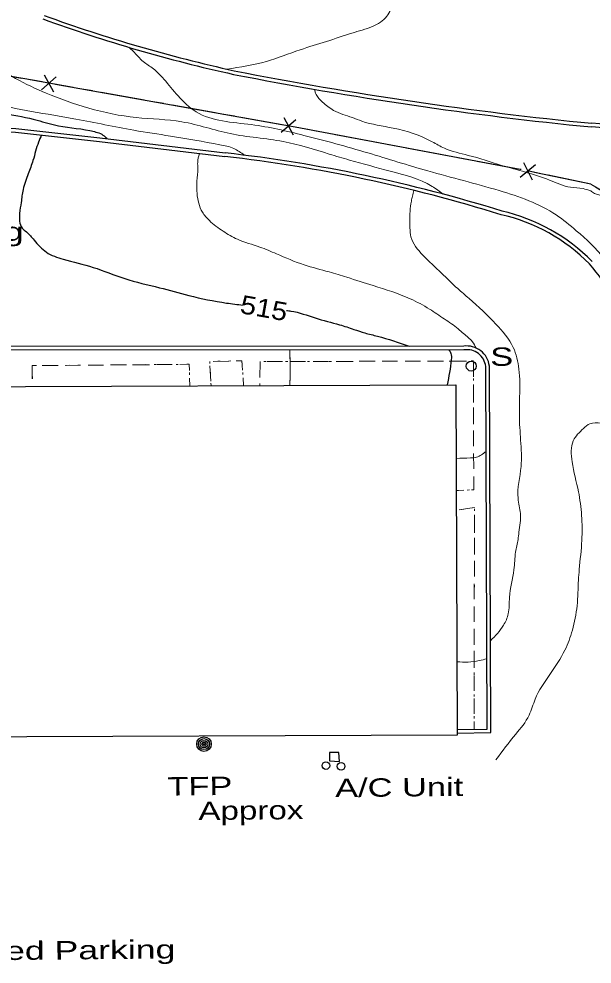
# Model space of a CAD drawing. Extents: x 2362213 to 2366494, y 6968794 to 6978110.
# Drawn here: x 2363724.2 to 2363873.9, y 6976167.5 to 6976414.2 of the extents above; entities that cross this region are included whole.
import ezdxf
from ezdxf.enums import TextEntityAlignment as Align

# ---------------------------------------------------------------- set-up
doc = ezdxf.new("R2010")
doc.units = 0
doc.header["$LTSCALE"] = 1.9
for name, pattern in [('DOTTED', [1.5, 0.3, -1.2]), ('LONG_DASH_SHORT_DASH', [9.9, 6, -1.2, 1.5, -1.2]), ('SHORT_DASHED', [2.7, 1.5, -1.2])]:
    doc.linetypes.add(name, pattern=pattern)
for name, color, linetype, lineweight in [('11', 7, 'Continuous', 25), ('13', 7, 'Continuous', 13), ('17', 7, 'Continuous', 25), ('2', 7, 'Continuous', 25), ('20', 7, 'Continuous', 25), ('21', 7, 'Continuous', 25), ('23', 7, 'Continuous', 25), ('31', 7, 'Continuous', 25), ('35', 7, 'Continuous', 13), ('36', 7, 'Continuous', 13)]:
    doc.layers.add(name, color=color, linetype=linetype, lineweight=lineweight)

msp = doc.modelspace()

# ---------------------------------------------------------------- linework, layer by layer
at = {"layer": '11'}
msp.add_lwpolyline([(2363568.529, 6976317.655), (2363838.301, 6976318.715), (2363838.662, 6976227.293), (2363568.89, 6976226.234)], close=True, dxfattribs=at)
at = {"layer": '13'}
for p, q in [((2363778.9, 6976324.898), (2363774.901, 6976324.81)), ((2363823.042, 6976324.839), (2363819.042, 6976324.831)), ((2363829.043, 6976324.866), (2363825.042, 6976324.848)), ((2363835.043, 6976324.883), (2363831.042, 6976324.875)), ((2363841.043, 6976324.9), (2363837.043, 6976324.892)), ((2363734.249, 6976323.743), (2363730.249, 6976323.715)), ((2363740.248, 6976323.79), (2363736.249, 6976323.762)), ((2363746.249, 6976323.838), (2363742.248, 6976323.809)), ((2363752.248, 6976323.895), (2363748.248, 6976323.857)), ((2363758.248, 6976323.942), (2363754.248, 6976323.914)), ((2363764.247, 6976323.999), (2363760.247, 6976323.961)), ((2363774.081, 6976323.673), (2363774.299, 6976319.674)), ((2363787.182, 6976324.587), (2363787.12, 6976320.587)), ((2363793.042, 6976324.743), (2363789.041, 6976324.735)), ((2363799.042, 6976324.76), (2363795.042, 6976324.752)), ((2363805.042, 6976324.787), (2363801.042, 6976324.769)), ((2363811.041, 6976324.805), (2363807.041, 6976324.796)), ((2363817.042, 6976324.822), (2363813.042, 6976324.814)), ((2363842.873, 6976320.727), (2363842.864, 6976324.728)), ((2363768.841, 6976318.443), (2363768.772, 6976320.442)), ((2363782.851, 6976318.497), (2363782.722, 6976320.495)), ((2363787.089, 6976318.587), (2363787.09, 6976318.517)), ((2363842.89, 6976314.728), (2363842.882, 6976318.728)), ((2363842.917, 6976308.728), (2363842.899, 6976312.728)), ((2363842.934, 6976302.727), (2363842.926, 6976306.728)), ((2363842.951, 6976296.727), (2363842.943, 6976300.727)), ((2363838.415, 6976291.095), (2363840.414, 6976291.184)), ((2363843.077, 6976286.669), (2363839.133, 6976286.021)), ((2363843.163, 6976280.788), (2363843.175, 6976284.79)), ((2363843.14, 6976274.788), (2363843.152, 6976278.788)), ((2363843.127, 6976268.789), (2363843.139, 6976272.789)), ((2363843.104, 6976262.788), (2363843.116, 6976266.788)), ((2363843.091, 6976256.787), (2363843.103, 6976260.788)), ((2363843.079, 6976250.786), (2363843.09, 6976254.787)), ((2363843.066, 6976244.787), (2363843.078, 6976248.787)), ((2363843.053, 6976238.786), (2363843.065, 6976242.787)), ((2363843.04, 6976232.785), (2363843.052, 6976236.785)), ((2363843.038, 6976228.785), (2363843.039, 6976230.785))]:
    msp.add_line(p, q, dxfattribs=at)
at = {"layer": '13', "linetype": 'DOTTED'}
for points in [[(2363782.851, 6976318.497), (2363782.419, 6976324.972), (2363774.021, 6976324.792), (2363774.371, 6976318.466)], [(2363838.415, 6976291.095), (2363842.973, 6976291.288), (2363842.863, 6976324.908), (2363787.181, 6976324.727), (2363787.09, 6976318.517)], [(2363768.841, 6976318.443), (2363768.648, 6976324.041), (2363727.679, 6976323.691), (2363727.691, 6976318.281)], [(2363843.038, 6976228.785), (2363843.177, 6976286.69), (2363838.434, 6976285.905)]]:
    msp.add_lwpolyline(points, dxfattribs=at)
at = {"layer": '13'}
for points in [[(2363782.583, 6976322.493), (2363782.419, 6976324.972), (2363780.9, 6976324.938)], [(2363728.249, 6976323.696), (2363727.679, 6976323.691), (2363727.682, 6976320.261)], [(2363768.703, 6976322.441), (2363768.648, 6976324.041), (2363766.247, 6976324.018)], [(2363842.413, 6976291.263), (2363842.973, 6976291.288), (2363842.96, 6976294.728)]]:
    msp.add_lwpolyline(points, dxfattribs=at)
at = {"layer": '17'}
for p, q in [((2363733.902, 6976399.064), (2363730.054, 6976395.688)), ((2363730.756, 6976399.624), (2363733.199, 6976395.127)), ((2363792.833, 6976386.555), (2363733.761, 6976397.083)), ((2363796.531, 6976387.88), (2363792.653, 6976384.533)), ((2363793.385, 6976388.47), (2363795.798, 6976383.943)), ((2363855.94, 6976376.735), (2363858.253, 6976372.167)), ((2363859.066, 6976376.085), (2363855.116, 6976372.827)), ((2363873.545, 6976371.043), (2363858.865, 6976374.113))]:
    msp.add_line(p, q, dxfattribs=at)
at = {"layer": '17', "linetype": 'LONG_DASH_SHORT_DASH'}
for points in [[(2363873.545, 6976371.043), (2363855.076, 6976374.907), (2363793.915, 6976386.365), (2363719.615, 6976399.608), (2363641.073, 6976414.261), (2363572.252, 6976426.636), (2363526.035, 6976435.556), (2363495.913, 6976440.79), (2363481.574, 6976443.734), (2363473.602, 6976444.928), (2363465.401, 6976443.98)], [(2363873.545, 6976371.043), (2363874.811, 6976370.385), (2363881.511, 6976366.277), (2363884.852, 6976362.97), (2363889.388, 6976357.143), (2363895.017, 6976347.796), (2363898.908, 6976336.183), (2363906.246, 6976314.412), (2363913.758, 6976296.292), (2363920.544, 6976281.085), (2363939.363, 6976255.993), (2363960.385, 6976230.752), (2363984.072, 6976199.658)]]:
    msp.add_lwpolyline(points, dxfattribs=at)
at = {"layer": '17'}
for points in [[(2363730.214, 6976397.719), (2363719.615, 6976399.608), (2363671.217, 6976408.638)], [(2363855.337, 6976374.85), (2363855.076, 6976374.907), (2363796.37, 6976385.909)], [(2363873.545, 6976371.043), (2363874.811, 6976370.385), (2363881.511, 6976366.277), (2363884.852, 6976362.97), (2363885.47, 6976362.166)]]:
    msp.add_lwpolyline(points, dxfattribs=at)
at = {"layer": '2'}
for p, q in [((2363840.346, 6976328.765), (2363565.553, 6976328.658)), ((2363840.345, 6976327.805), (2363565.553, 6976327.698))]:
    msp.add_line(p, q, dxfattribs=at)
for points in [[(2363716.905, 6976384.842), (2363723.299, 6976384.623), (2363745.203, 6976382.161), (2363777.962, 6976378.253)], [(2363716.936, 6976385.802), (2363723.37, 6976385.583), (2363745.314, 6976383.112), (2363778.073, 6976379.204)], [(2363838.639, 6976228.703), (2363846.498, 6976228.858), (2363846.086, 6976323.578)], [(2363838.658, 6976227.743), (2363847.467, 6976227.917), (2363847.045, 6976323.587)]]:
    msp.add_lwpolyline(points, dxfattribs=at)
for centre, radius, start, end in [((2363865.346, 6976785.483), 395.058, 250.03282, 257.55374), ((2363865.346, 6976785.483), 394.098, 250.03282, 257.55374), ((2363971.891, 6977379.515), 998.38, 258.93176, 264.35807), ((2363971.891, 6977379.515), 997.42, 258.93176, 264.35807), ((2363446.466, 6970015.596), 6385.647, 85.88154, 86.16254), ((2363446.466, 6970015.596), 6384.687, 85.88154, 86.16254), ((2363733.974, 6975989.821), 391.874, 72.71881, 83.53909), ((2363733.974, 6975989.821), 390.914, 72.71881, 83.53909), ((2363839.683, 6976317.272), 46.986, 44.52251, 77.19154), ((2363839.683, 6976317.272), 47.946, 44.52251, 77.19154), ((2363837.348, 6976318.237), 48.031, 15.6658, 41.74776), ((2363841.145, 6976322.875), 5.944, 6.89231, 97.72428), ((2363841.145, 6976322.875), 4.984, 6.89231, 97.72428)]:
    msp.add_arc(centre, radius, start, end, dxfattribs=at)
at = {"layer": '20'}
for radius in [1.9, 1.442, 0.973, 0.539, 0.192]:
    msp.add_circle((2363772.511, 6976224.914), radius, dxfattribs=at)
at = {"layer": '21'}
msp.add_circle((2363842.315, 6976323.573), 1.3, dxfattribs=at)
at = {"layer": '23'}
msp.add_lwpolyline([(2363805.274, 6976222.746), (2363805.294, 6976220.596), (2363807.895, 6976220.421), (2363807.743, 6976222.759)], close=True, dxfattribs=at)
for centre in [(2363804.356, 6976219.327), (2363808.318, 6976219.124)]:
    msp.add_circle(centre, 1, dxfattribs=at)
at = {"layer": '31'}
for points in [[(2363687.536, 6976396.303), (2363692.366, 6976395.199), (2363700.808, 6976393.019), (2363710.362, 6976390.529), (2363720.773, 6976389.348), (2363728.939, 6976387.727), (2363734.514, 6976386.27), (2363743.907, 6976384.769), (2363746.732, 6976383.376), (2363747.126, 6976382.9)], [(2363730.096, 6976383.857), (2363729.294, 6976382.01), (2363727.859, 6976377.246), (2363726.592, 6976373.754), (2363725.281, 6976369.681), (2363724.754, 6976366.245), (2363724.371, 6976363.402), (2363725.047, 6976359.598), (2363726.137, 6976358.599), (2363728.137, 6976356.458), (2363731.367, 6976353.288), (2363735.715, 6976351.479), (2363743.565, 6976349.344), (2363751.814, 6976346.402), (2363760.866, 6976344.028), (2363768.587, 6976342.001), (2363778.386, 6976340.035), (2363782.711, 6976339.486)], [(2363794.085, 6976338.075), (2363795.217, 6976337.935), (2363801.544, 6976336.146), (2363807.94, 6976334.356), (2363811.663, 6976333.162), (2363814.532, 6976332.219), (2363817.82, 6976331.38), (2363826.085, 6976328.759)], [(2363836.505, 6976327.808), (2363837.024, 6976326.853), (2363837.089, 6976325.253), (2363836.052, 6976318.703)]]:
    msp.add_spline(points, degree=3, dxfattribs=at)
at = {"layer": '35'}
for points in [[(2363665.808, 6976435.897), (2363665.919, 6976434.768), (2363666.153, 6976433.191), (2363666.314, 6976430.992), (2363666.145, 6976426.72), (2363665.963, 6976424.849), (2363665.087, 6976420.2), (2363663.69, 6976415.717), (2363662.882, 6976412.358), (2363662.713, 6976411.206), (2363663.338, 6976409.593), (2363666.495, 6976407.783), (2363676.361, 6976403.967), (2363689.155, 6976400.638), (2363697.557, 6976398.178), (2363713.631, 6976393.721), (2363716.36, 6976392.717), (2363727.497, 6976390.022), (2363739.046, 6976388.042), (2363754.215, 6976385.117), (2363763.749, 6976383.598), (2363776.612, 6976381.35), (2363780.312, 6976380.355), (2363783.068, 6976378.612)], [(2363820.888, 6976430.354), (2363821.185, 6976428.567), (2363822.194, 6976425.516), (2363822.362, 6976423.598), (2363822.242, 6976421.547), (2363821.782, 6976418.322), (2363820.275, 6976414.878), (2363816.52, 6976412.211), (2363811.116, 6976410.46), (2363804.527, 6976408.287), (2363797.617, 6976406.121), (2363788.815, 6976403.087), (2363778.505, 6976401.069)], [(2363708.819, 6976422.297), (2363710.519, 6976421.253), (2363712.34, 6976420.1), (2363714.323, 6976418.729), (2363715.71, 6976416.852), (2363717.526, 6976414.199), (2363718.19, 6976408.545), (2363718.641, 6976405.299), (2363720.14, 6976401.123), (2363723.315, 6976398.644), (2363731.272, 6976394.839), (2363742.419, 6976390.884), (2363754.814, 6976388.442), (2363766.764, 6976387.327), (2363779.325, 6976384.246), (2363793.225, 6976382.178), (2363805.227, 6976378.903), (2363810.511, 6976377.353), (2363821.13, 6976374.454), (2363832.107, 6976370.468), (2363834.968, 6976368.454)], [(2363752.879, 6976406.775), (2363754.009, 6976405.756), (2363756.655, 6976403.051), (2363759.293, 6976401.176), (2363762.048, 6976398.432), (2363765.739, 6976394.097), (2363770.48, 6976389.911), (2363784.872, 6976386.579), (2363798.63, 6976383.79), (2363815.294, 6976379.218), (2363831.019, 6976374.498), (2363849.65, 6976369.364), (2363864.501, 6976363.026), (2363869.76, 6976358.896), (2363876.999, 6976351.595), (2363881.126, 6976344.713), (2363883.59, 6976340.127), (2363885.881, 6976332.669), (2363887.899, 6976323.466), (2363889.062, 6976316.828), (2363891.214, 6976306.088), (2363893.999, 6976296.104), (2363894.644, 6976288.3)], [(2363801.376, 6976395.807), (2363801.799, 6976394.431), (2363803.498, 6976392.477), (2363806.368, 6976390.283), (2363811.265, 6976388.431), (2363813.715, 6976387.504), (2363821.953, 6976385.672), (2363832.136, 6976382.129), (2363835.294, 6976380.419), (2363841.552, 6976378.568), (2363850.227, 6976375.961), (2363862.734, 6976372.12), (2363868.222, 6976370.252), (2363871.516, 6976369.893), (2363873.521, 6976369.352)], [(2363771.324, 6976379.04), (2363770.866, 6976376.715), (2363770.9, 6976375.216), (2363770.673, 6976371.813), (2363770.704, 6976368.542), (2363772.09, 6976363.746), (2363773.921, 6976361.544), (2363777.507, 6976358.778), (2363781.247, 6976356.673), (2363787.116, 6976354.619), (2363791.424, 6976352.88), (2363798.662, 6976349.999), (2363805.2, 6976348.141), (2363809.832, 6976346.744), (2363816.704, 6976344.589), (2363826.367, 6976341.132), (2363831.422, 6976338.44), (2363835.258, 6976335.877), (2363838.923, 6976333.281), (2363840.314, 6976332.065), (2363842.595, 6976329.956), (2363843.611, 6976328.286)], [(2363827.338, 6976369.422), (2363826.963, 6976367.908), (2363826.685, 6976366.635), (2363826.351, 6976363.893), (2363826.261, 6976361.772), (2363826.311, 6976359.643), (2363826.574, 6976357.275), (2363829.658, 6976352.534), (2363834.564, 6976347.831), (2363838.783, 6976343.8), (2363841.747, 6976341.219), (2363848.761, 6976334.545), (2363853.278, 6976328.458), (2363854.783, 6976322.781), (2363854.961, 6976315.613), (2363854.887, 6976310.812), (2363855.219, 6976304.225), (2363855.335, 6976297.325), (2363854.544, 6976289.068), (2363855.152, 6976285.084), (2363854.788, 6976280.189), (2363854.536, 6976278.317), (2363853.897, 6976275.02), (2363853.482, 6976270.437), (2363852.301, 6976263.196), (2363851.991, 6976258.921), (2363850.74, 6976255.959), (2363847.358, 6976251.867)], [(2363873.521, 6976369.352), (2363874.538, 6976368.651), (2363875.069, 6976368.476), (2363880.984, 6976364.843), (2363883.07, 6976363.213), (2363885.165, 6976356.403), (2363888.555, 6976346.894), (2363891.363, 6976340.831), (2363894.384, 6976329.269), (2363898.171, 6976318.035), (2363903.178, 6976307.872), (2363909.902, 6976295.906), (2363915.335, 6976281.917), (2363919.346, 6976271.354), (2363923.916, 6976260.937), (2363928.305, 6976253.678), (2363935.565, 6976244.228), (2363940.051, 6976236.279), (2363940.504, 6976232.773)], [(2363889.133, 6976305.158), (2363887.554, 6976306.033), (2363886.155, 6976307.01), (2363884.085, 6976308.1), (2363879.221, 6976308.424), (2363876.199, 6976308.675), (2363873.28, 6976308.527), (2363871.612, 6976307.282), (2363868.962, 6976304.106), (2363868.654, 6976298.612), (2363870.319, 6976290.778), (2363871.148, 6976284.606), (2363871.2, 6976278.095), (2363870.532, 6976270.49), (2363870.328, 6976267.747), (2363869.962, 6976261.034), (2363868.733, 6976254.631), (2363866.772, 6976249.453), (2363862.823, 6976243.105), (2363859.024, 6976236.687), (2363857.424, 6976232.442), (2363853.93, 6976227.519), (2363848.764, 6976220.85)], [(2363846.178, 6976301.298), (2363843.702, 6976299.794), (2363842.094, 6976299.589), (2363838.375, 6976299.494)], [(2363846.413, 6976247.179), (2363844.357, 6976246.709), (2363841.531, 6976246.292), (2363838.59, 6976246.424)]]:
    msp.add_spline(points, degree=3, dxfattribs=at)
at = {"layer": '36'}
msp.add_lwpolyline([(2363794.933, 6976327.782), (2363794.956, 6976326.472), (2363794.988, 6976325.162), (2363795.002, 6976324.712), (2363795.027, 6976324.262), (2363795.054, 6976321.402), (2363794.951, 6976318.542)], dxfattribs=at)
at = {"layer": '36', "linetype": 'SHORT_DASHED'}
msp.add_spline([(2363794.933, 6976327.782), (2363794.988, 6976325.162), (2363795.027, 6976324.262), (2363794.951, 6976318.542)], degree=3, dxfattribs=at)

# ---------------------------------------------------------------- texts
at = {"layer": '2', "width": 1.45}
for p in [(2363664.911, 6976355.715), (2363704.537, 6976168.413)]:
    msp.add_text('Paved Parking', height=4.8, rotation=0.546, dxfattribs=at).set_placement(p)
at = {"layer": '20'}
for s, width, p in [('  TFP', 1.4, (2363757.979, 6976211.434)), ('Approx', 1.35, (2363771.06, 6976205.088))]:
    msp.add_text(s, height=4.8, rotation=0.546, dxfattribs=dict(at, width=width)).set_placement(p)
at = {"layer": '21', "width": 1.4}
msp.add_text('  S', height=4.8, rotation=0.546, dxfattribs=at).set_placement((2363842.306, 6976323.562))
at = {"layer": '23', "width": 1.4}
msp.add_text('A/C Unit ', height=4.8, rotation=0.546, dxfattribs=at).set_placement((2363806.785, 6976211.079))
at = {"layer": '31', "width": 1.15}
msp.add_text(' 515 ', height=4.8, rotation=349.878, dxfattribs=at).set_placement((2363787.776, 6976336.35), align=Align.CENTER)

doc.saveas('drawing.dxf')
